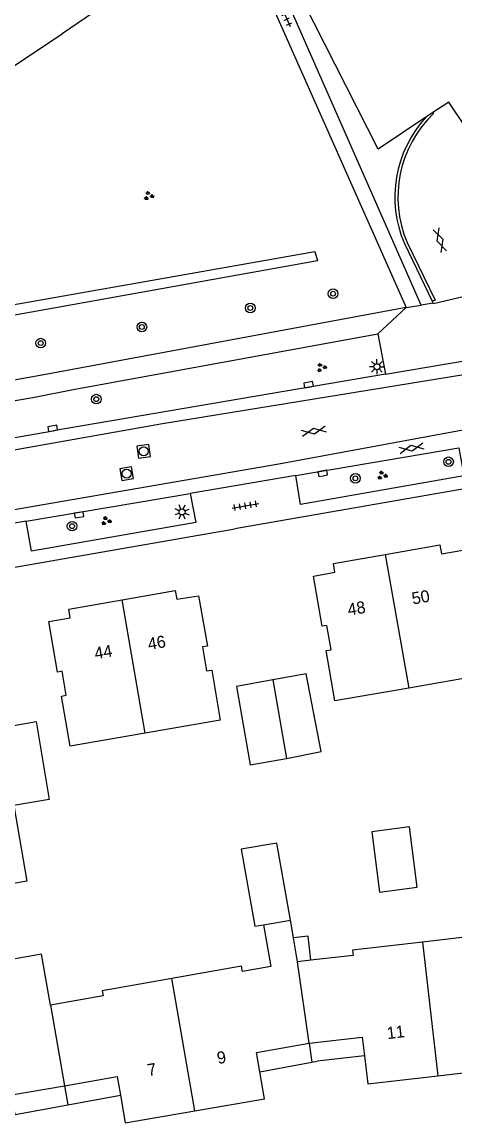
# Model space of a CAD drawing. Extents: x 137999 to 141000, y 397500 to 400501.
# Drawn here: x 138204.7 to 138240.6, y 399144.5 to 399235.9 of the extents above; entities that cross this region are included whole.
import ezdxf

# ---------------------------------------------------------------- set-up
doc = ezdxf.new("R2010")
doc.units = 0
for name, color, linetype in [('gg-afsc-erfafscheiding', 7, 'Continuous'), ('gg-afsc-muur', 7, 'Continuous'), ('gg-anno-huisnummerreeks BGT', 7, 'Continuous'), ('gg-bbg-bijgebouw', 7, 'Continuous'), ('gg-bbg-gedigitaliseerde bebouwing', 7, 'Continuous'), ('gg-bbg-gedigitaliseerde bijgebouw', 7, 'Continuous'), ('gg-bbg-hoofdgebouw', 7, 'Continuous'), ('gg-bbg-luifel en loopbrug', 7, 'Continuous'), ('gg-bbg-tussenscheiding', 7, 'Continuous'), ('gg-knt-verharding', 7, 'Continuous'), ('gg-knt-verharding nz', 7, 'Continuous'), ('gt-grn-groengrens', 7, 'Continuous'), ('gt-grn-weggrens', 7, 'Continuous'), ('gt-symb-boom', 7, 'Continuous'), ('gt-symb-gesloten verharding', 7, 'Continuous'), ('gt-symb-groenvak', 7, 'Continuous'), ('gt-symb-kolk', 7, 'Continuous'), ('gt-symb-lichtmast', 7, 'Continuous'), ('gt-symb-rioolschacht', 7, 'Continuous'), ('gt-symb-tegel verharding', 7, 'Continuous')]:
    doc.layers.add(name, color=color, linetype=linetype)

# ---------------------------------------------------------------- blocks, each defined once
blk = doc.blocks.new('gt0-TEG1')
at = {"layer": 'gt-symb-tegel verharding'}
for p, q in [((-1.125, 0), (1.125, 0)), ((-0.9, -0.25), (-0.9, 0.25)), ((-0.45, -0.25), (-0.45, 0.25)), ((0, -0.25), (0, 0.25)), ((0.45, -0.25), (0.45, 0.25)), ((0.9, -0.25), (0.9, 0.25))]:
    blk.add_line(p, q, dxfattribs=at)
blk = doc.blocks.new('gt0-GESVH1')
at = {"layer": 'gt-symb-gesloten verharding'}
for p, q in [((-0.992, -0.261), (0.008, 0.239)), ((0.008, -0.261), (-0.992, 0.239)), ((0.008, 0.239), (1.008, -0.261)), ((1.008, 0.239), (0.008, -0.261))]:
    blk.add_line(p, q, dxfattribs=at)
blk = doc.blocks.new('gt0-GRVAK')
at = {"layer": 'gt-symb-groenvak'}
for p, q in [((-0.11, 0.189), (-0.228, 0.24)), ((-0.182, 0.153), (0.088, 0.153)), ((-0.091, 0.211), (-0.156, 0.322)), ((-0.047, 0.214), (-0.047, 0.393)), ((-0.004, 0.211), (0.061, 0.322)), ((0.015, 0.189), (0.133, 0.24)), ((0.262, -0.052), (0.197, 0.059)), ((0.305, -0.049), (0.305, 0.13)), ((0.349, -0.052), (0.414, 0.059)), ((-0.245, -0.228), (-0.363, -0.177)), ((-0.318, -0.264), (-0.047, -0.264)), ((-0.226, -0.206), (-0.291, -0.095)), ((-0.183, -0.203), (-0.183, -0.024)), ((-0.139, -0.206), (-0.074, -0.095)), ((-0.12, -0.228), (-0.002, -0.177)), ((0.243, -0.074), (0.125, -0.023)), ((0.17, -0.11), (0.441, -0.11)), ((0.368, -0.074), (0.486, -0.023))]:
    blk.add_line(p, q, dxfattribs=at)
blk = doc.blocks.new('gt0-BOOM')
at = {"layer": 'gt-symb-boom'}
for radius in [0.4, 0.2]:
    blk.add_circle((0, 0), radius, dxfattribs=at)
blk = doc.blocks.new('gt0-KOLK')
at = {"layer": 'gt-symb-kolk'}
blk.add_lwpolyline([(0, 0), (0.375, 0), (0.375, 0.4), (-0.375, 0.4), (-0.375, 0), (0, 0)], dxfattribs=at)
blk = doc.blocks.new('gt0-RS')
at = {"layer": 'gt-symb-rioolschacht'}
blk.add_lwpolyline([(-0.5, -0.5), (0.5, -0.5), (0.5, 0.5), (-0.5, 0.5)], close=True, dxfattribs=at)
blk.add_circle((0, 0), 0.375, dxfattribs=at)
blk = doc.blocks.new('gt0-LMAST')
at = {"layer": 'gt-symb-lichtmast'}
for p, q in [((-0.182, 0.173), (-0.447, 0.438)), ((-0.005, 0.246), (-0.005, 0.621)), ((0.172, 0.173), (0.437, 0.438)), ((-0.255, -0.004), (-0.63, -0.004)), ((-0.182, -0.181), (-0.447, -0.446)), ((-0.005, -0.254), (-0.005, -0.629)), ((0.437, -0.446), (0.172, -0.181)), ((0.245, -0.004), (0.62, -0.004))]:
    blk.add_line(p, q, dxfattribs=at)
blk.add_circle((-0.005, -0.004), 0.25, dxfattribs=at)

msp = doc.modelspace()

# ---------------------------------------------------------------- linework, layer by layer
at = {"layer": 'gg-afsc-erfafscheiding'}
for p in [(138222.163, 399244.66), (138162.505, 399204.745)]:
    msp.add_line(p, (138208.008, 399234.964), dxfattribs=at)
at = {"layer": 'gg-afsc-muur'}
for p, q in [((138238.745, 399228.433), (138238.806, 399228.342)), ((138236.391, 399217.549), (138238.701, 399212.779))]:
    msp.add_line(p, q, dxfattribs=at)
msp.add_lwpolyline([(138236.621, 399217.647), (138238.95, 399212.839), (138238.701, 399212.779)], dxfattribs=at)
for radius, start, end in [(9.862, 137.70895, 203.05501), (9.612, 133.85359, 203.05303)]:
    msp.add_arc((138245.465, 399221.411), radius, start, end, dxfattribs=at)
at = {"layer": 'gg-bbg-bijgebouw'}
for points in [[(138225.474, 399181.319), (138222.453, 399180.763), (138223.605, 399174.259), (138226.623, 399174.789)], [(138226.623, 399174.789), (138229.494, 399175.368), (138228.256, 399181.831), (138225.474, 399181.319)], [(138202.91, 399177.348), (138205.864, 399177.873), (138206.934, 399171.395), (138203.991, 399170.881)]]:
    msp.add_lwpolyline(points, dxfattribs=at)
at = {"layer": 'gg-bbg-gedigitaliseerde bebouwing'}
for p, q in [((138224.705, 399160.985), (138226.932, 399161.373)), ((138224.705, 399160.985), (138225.304, 399157.529)), ((138211.401, 399155.075), (138207.026, 399154.316))]:
    msp.add_line(p, q, dxfattribs=at)
msp.add_lwpolyline([(138207.026, 399154.316), (138206.291, 399158.54), (138201.936, 399157.782), (138201.998, 399157.425)], dxfattribs=at)
at = {"layer": 'gg-bbg-gedigitaliseerde bijgebouw'}
msp.add_line((138227.188, 399159.896), (138226.932, 399161.373), dxfattribs=at)
msp.add_lwpolyline([(138228.636, 399158.046), (138228.413, 399160.034), (138227.188, 399159.896)], dxfattribs=at)
at = {"layer": 'gg-bbg-hoofdgebouw'}
msp.add_line((138238.745, 399228.433), (138238.17, 399228.047), dxfattribs=at)
for points in [[(138238.17, 399228.047), (138234.205, 399225.388), (138226.21, 399241.234), (138229.968, 399243.578), (138228.307, 399246.273)], [(138242.594, 399225.051), (138242.646, 399225.085), (138242.566, 399225.215), (138242.738, 399225.337), (138240.07, 399229.301), (138238.745, 399228.433)], [(138234.81, 399191.746), (138239.334, 399192.532), (138239.462, 399191.793), (138241.236, 399192.101), (138241.962, 399187.924), (138241.577, 399187.857), (138241.927, 399185.847), (138242.311, 399185.914), (138243.037, 399181.737), (138236.747, 399180.644)], [(138236.747, 399180.644), (138230.633, 399179.581), (138229.917, 399183.76), (138230.311, 399183.829), (138229.961, 399185.839), (138229.567, 399185.77), (138228.841, 399189.947), (138230.634, 399190.259), (138230.506, 399190.998), (138234.81, 399191.746)], [(138212.985, 399187.975), (138217.389, 399188.743), (138217.51, 399188.023), (138219.321, 399188.309), (138220.065, 399184.124), (138219.641, 399184.057), (138219.986, 399182.061), (138220.41, 399182.128), (138221.108, 399177.985), (138214.888, 399176.898)], [(138214.888, 399176.898), (138208.682, 399175.814), (138207.96, 399179.972), (138208.344, 399180.039), (138207.998, 399182.038), (138207.62, 399181.972), (138206.89, 399186.162), (138208.68, 399186.483), (138208.559, 399187.203), (138212.985, 399187.975)], [(138249.034, 399160.454), (138243.762, 399159.763), (138243.726, 399160.232), (138237.905, 399159.554)], [(138237.905, 399159.554), (138232.094, 399158.878), (138232.145, 399158.441), (138228.636, 399158.046)], [(138225.304, 399157.529), (138222.951, 399157.114), (138222.875, 399157.547), (138217.104, 399156.528)], [(138217.104, 399156.528), (138211.325, 399155.508), (138211.401, 399155.075)], [(138224.398, 399148.783), (138224.121, 399150.388), (138228.484, 399151.155)], [(138228.484, 399151.155), (138232.884, 399151.647), (138233.072, 399150.095)], [(138239.173, 399148.455), (138244.996, 399149.139), (138244.728, 399151.419)], [(138233.072, 399150.095), (138233.353, 399147.771), (138239.173, 399148.455)], [(138208.191, 399147.624), (138212.573, 399148.385), (138212.839, 399146.837)], [(138219.009, 399145.531), (138224.786, 399146.535), (138224.398, 399148.783)], [(138204.104, 399145.232), (138203.816, 399146.865), (138208.191, 399147.624)], [(138212.839, 399146.837), (138213.237, 399144.528), (138219.009, 399145.531)]]:
    msp.add_lwpolyline(points, dxfattribs=at)
at = {"layer": 'gg-bbg-luifel en loopbrug'}
for p, q in [((138228.484, 399151.155), (138228.707, 399149.574)), ((138233.072, 399150.095), (138229.159, 399149.657)), ((138224.398, 399148.783), (138228.707, 399149.574)), ((138228.707, 399149.574), (138229.159, 399149.657)), ((138208.191, 399147.624), (138208.483, 399146.037)), ((138208.483, 399146.037), (138212.839, 399146.837)), ((138204.104, 399145.232), (138208.483, 399146.037))]:
    msp.add_line(p, q, dxfattribs=at)
for points in [[(138203.991, 399170.881), (138205.079, 399164.599), (138201.068, 399163.905), (138199.931, 399170.47), (138200.988, 399170.653)], [(138233.7, 399168.716), (138234.33, 399163.708), (138237.456, 399164.101), (138236.825, 399169.11), (138233.7, 399168.716)], [(138226.932, 399161.373), (138225.822, 399167.775), (138222.866, 399167.263), (138223.976, 399160.858), (138224.705, 399160.985)]]:
    msp.add_lwpolyline(points, dxfattribs=at)
at = {"layer": 'gg-bbg-tussenscheiding'}
for p, q in [((138234.81, 399191.746), (138236.747, 399180.644)), ((138214.888, 399176.898), (138212.985, 399187.975)), ((138225.474, 399181.319), (138226.623, 399174.789)), ((138227.53, 399157.922), (138227.188, 399159.896)), ((138237.905, 399159.554), (138239.173, 399148.455)), ((138228.636, 399158.046), (138227.53, 399157.922)), ((138228.484, 399151.155), (138227.53, 399157.922)), ((138219.009, 399145.531), (138217.104, 399156.528)), ((138207.026, 399154.316), (138208.191, 399147.624))]:
    msp.add_line(p, q, dxfattribs=at)
at = {"layer": 'gg-knt-verharding'}
for p, q in [((138222.494, 399243.913), (138236.542, 399212.247)), ((138236.542, 399212.247), (138206.49, 399206.64)), ((138238.787, 399212.601), (138237.783, 399212.441)), ((138234.197, 399210.054), (138234.826, 399206.713)), ((138206.49, 399206.64), (138159.538, 399198.453)), ((138234.826, 399206.713), (138207.252, 399202.01)), ((138290.356, 399205.722), (138222.319, 399193.878)), ((138160.581, 399196.928), (138205.58, 399204.78)), ((138178.299, 399197.007), (138207.252, 399202.01)), ((138227.388, 399198.291), (138240.898, 399200.599)), ((138227.388, 399198.291), (138218.635, 399196.8)), ((138205.024, 399194.493), (138218.635, 399196.8)), ((138155.099, 399182.118), (138222.319, 399193.878)), ((138205.024, 399194.493), (138201.279, 399193.866))]:
    msp.add_line(p, q, dxfattribs=at)
for points in [[(138237.783, 399212.441), (138224.162, 399243.443), (138228.307, 399246.273)], [(138244.389, 399213.967), (138244.417, 399213.868), (138238.819, 399212.535), (138238.787, 399212.601)], [(138205.58, 399204.78), (138208.916, 399205.422), (138234.197, 399210.054)], [(138234.826, 399206.713), (138245.948, 399208.586), (138249.939, 399209.39), (138252.85, 399210.024)], [(138240.898, 399200.599), (138241.334, 399198.278), (138227.764, 399195.872), (138227.388, 399198.291)], [(138218.635, 399196.8), (138219.082, 399194.389), (138205.462, 399192.009), (138205.024, 399194.493)]]:
    msp.add_lwpolyline(points, dxfattribs=at)
at = {"layer": 'gg-knt-verharding nz'}
for points in [[(138164.243, 399193.356), (138216.323, 399202.605), (138247.101, 399207.635), (138252.493, 399208.62), (138260.367, 399210.157), (138264.753, 399211.288), (138269.277, 399212.693), (138277.81, 399215.64), (138288.639, 399219.971)], [(138165.082, 399188.734), (138225.986, 399199.273), (138251.275, 399203.949), (138260.085, 399205.821), (138269.806, 399208.452), (138279.293, 399211.756), (138288.638, 399215.369)]]:
    msp.add_lwpolyline(points, dxfattribs=at)
at = {"layer": 'gt-grn-groengrens'}
msp.add_lwpolyline([(138167.494, 399206.051), (138228.965, 399216.895), (138229.189, 399216.127), (138167.69, 399205.069), (138167.494, 399206.051)], dxfattribs=at)
at = {"layer": 'gt-grn-weggrens'}
for p, q in [((138236.542, 399212.247), (138234.197, 399210.054)), ((138236.542, 399212.247), (138237.783, 399212.441)), ((138238.701, 399212.779), (138238.787, 399212.601))]:
    msp.add_line(p, q, dxfattribs=at)

# ---------------------------------------------------------------- block references
at = {"layer": 'gt-symb-boom'}
for p in [(138230.479, 399213.388), (138223.617, 399212.203), (138214.619, 399210.627), (138206.23, 399209.287), (138210.838, 399204.635), (138240.052, 399199.43), (138232.33, 399198.06), (138208.83, 399194.086)]:
    msp.add_blockref('gt0-BOOM', p, dxfattribs=at)
at = {"layer": 'gt-symb-gesloten verharding'}
for p, rotation in [((138239.334, 399217.816), 108.2356914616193), ((138228.878, 399201.984), 10.48938981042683), ((138236.971, 399200.569), 10.48938981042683)]:
    msp.add_blockref('gt0-GESVH1', p, dxfattribs=dict(at, rotation=rotation))
at = {"layer": 'gt-symb-groenvak'}
for p, rotation in [((138215.175, 399221.514), 1.3748347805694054), ((138229.493, 399207.249), 11.478482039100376)]:
    msp.add_blockref('gt0-GRVAK', p, dxfattribs=dict(at, rotation=rotation))
for p in [(138234.544, 399198.295), (138211.646, 399194.523)]:
    msp.add_blockref('gt0-GRVAK', p, dxfattribs=at)
at = {"layer": 'gt-symb-kolk'}
for p, rotation in [((138228.476, 399205.636), 9.613025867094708), ((138207.252, 399202.01), 9.669505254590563), ((138229.656, 399198.276), 9.792146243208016), ((138209.442, 399194.829), 9.792146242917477)]:
    msp.add_blockref('gt0-KOLK', p, dxfattribs=dict(at, rotation=rotation))
at = {"layer": 'gt-symb-lichtmast'}
msp.add_blockref('gt0-LMAST', (138234.116, 399207.329), dxfattribs=at)
at = {"layer": 'gt-symb-lichtmast', "rotation": -68.02828960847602}
msp.add_blockref('gt0-LMAST', (138217.958, 399195.267), dxfattribs=at)
at = {"layer": 'gt-symb-rioolschacht'}
for p, rotation in [((138214.764, 399200.298), 8.680850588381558), ((138213.354, 399198.446), 9.613025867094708)]:
    msp.add_blockref('gt0-RS', p, dxfattribs=dict(at, rotation=rotation))
at = {"layer": 'gt-symb-tegel verharding'}
for p, rotation in [((138226.458, 399236.599), -65.6651257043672), ((138223.209, 399195.784), 9.725965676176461)]:
    msp.add_blockref('gt0-TEG1', p, dxfattribs=dict(at, rotation=rotation))

# ---------------------------------------------------------------- texts
at = {"layer": 'gg-anno-huisnummerreeks BGT'}
for s, rotation, p in [('50', 9.8, (138237.095, 399187.576)), ('48', 9.8, (138231.768, 399186.65)), ('46', 9.9, (138215.198, 399183.792)), ('44', 9.9, (138210.77, 399183.02)), ('11', 6.7, (138234.991, 399151.487)), ('9', 9.8, (138220.938, 399149.419)), ('7', 9.8, (138215.159, 399148.415))]:
    msp.add_text(s, height=1, rotation=rotation, dxfattribs=at).set_placement(p)

doc.saveas('drawing.dxf')
